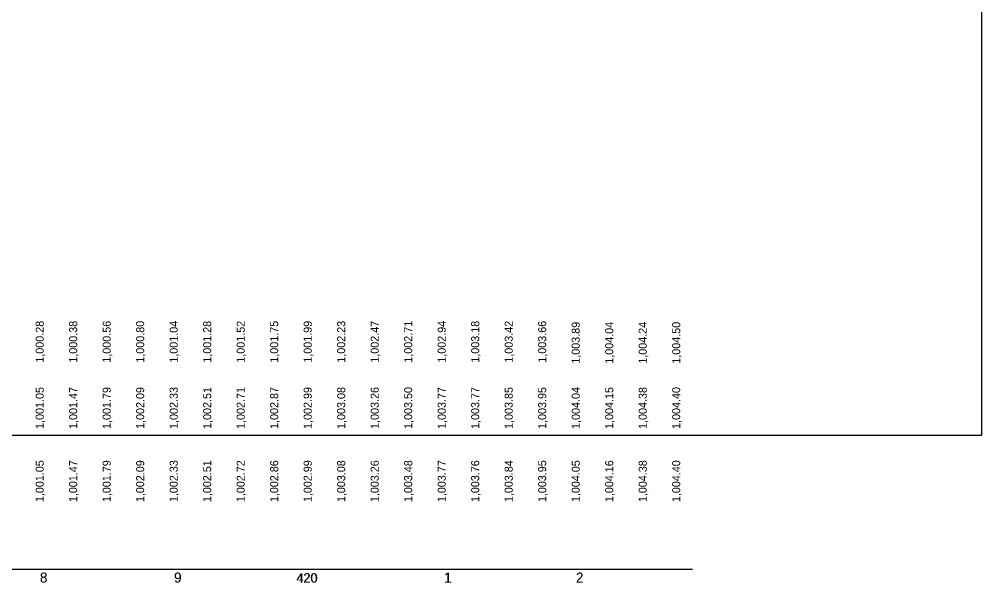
# Model space of a CAD drawing. Extents: x 150 to 16976893, y 3102 to 12559827.
# Drawn here: x 16976175 to 16976893, y 12558429 to 12558849 of the extents above; entities that cross this region are included whole.
import ezdxf

# ---------------------------------------------------------------- set-up
doc = ezdxf.new("R2010")
doc.units = 0
for name, color, linetype in [('Default', 7, 'Continuous'), ('Level 56', 7, 'Continuous'), ('RD_DDB_StaTX', 7, 'Continuous'), ('RD_DDB_StripGrade_EX', 7, 'Continuous'), ('RD_GPK_Profile_Cell', 7, 'Continuous')]:
    doc.layers.add(name, color=color, linetype=linetype)

msp = doc.modelspace()

# ---------------------------------------------------------------- linework, layer by layer
at = {"layer": 'Default'}
msp.add_lwpolyline([(16975392.9, 12558539.31), (16976892.9, 12558539.31), (16976892.9, 12559537.53), (16975392.9, 12559537.53)], close=True, dxfattribs=at)
at = {"layer": 'RD_GPK_Profile_Cell'}
msp.add_line((16972208.1, 12558439.31), (16976677.07, 12558439.31), dxfattribs=at)

# ---------------------------------------------------------------- texts
at = {"layer": 'Level 56'}
for s, p in [('1,000.28', (16976192.9, 12558593.29)), ('1,000.38', (16976217.9, 12558593.29)), ('1,000.56', (16976242.9, 12558593.29)), ('1,000.80', (16976267.9, 12558593.29)), ('1,001.04', (16976292.9, 12558593.29)), ('1,001.28', (16976317.9, 12558593.29)), ('1,001.52', (16976342.9, 12558593.29)), ('1,001.75', (16976367.9, 12558593.29)), ('1,001.99', (16976392.9, 12558593.29)), ('1,002.23', (16976417.9, 12558593.29)), ('1,002.47', (16976442.9, 12558593.29)), ('1,002.71', (16976467.9, 12558593.29)), ('1,002.94', (16976492.9, 12558593.29)), ('1,003.18', (16976517.9, 12558593.29)), ('1,003.42', (16976542.9, 12558593.29)), ('1,003.66', (16976567.9, 12558593.29)), ('1,003.89', (16976592.9, 12558592.52)), ('1,004.04', (16976617.9, 12558592.52)), ('1,004.24', (16976642.9, 12558592.52)), ('1,004.50', (16976667.9, 12558592.52)), ('1,001.05', (16976192.9, 12558489.31)), ('1,001.47', (16976217.9, 12558489.31)), ('1,001.79', (16976242.9, 12558489.31)), ('1,002.09', (16976267.9, 12558489.31)), ('1,002.33', (16976292.9, 12558489.31)), ('1,002.51', (16976317.9, 12558489.31)), ('1,002.72', (16976342.9, 12558489.31)), ('1,002.86', (16976367.9, 12558489.31)), ('1,002.99', (16976392.9, 12558489.31)), ('1,003.08', (16976417.9, 12558489.31)), ('1,003.26', (16976442.9, 12558489.31)), ('1,003.48', (16976467.9, 12558489.31)), ('1,003.77', (16976492.9, 12558489.31)), ('1,003.76', (16976517.9, 12558489.31)), ('1,003.84', (16976542.9, 12558489.31)), ('1,003.95', (16976567.9, 12558489.31)), ('1,004.05', (16976592.9, 12558489.31)), ('1,004.16', (16976617.9, 12558489.31)), ('1,004.38', (16976642.9, 12558489.31)), ('1,004.40', (16976667.9, 12558489.31))]:
    msp.add_text(s, height=6, rotation=90, dxfattribs=at).set_placement(p)
at = {"layer": 'RD_DDB_StaTX'}
for s, height, p in [('8', 7.5, (16976190.05, 12558429.31)), ('8', 7.5, (16976190.12, 12558429.31)), ('9', 7.5, (16976290.12, 12558429.31)), ('9', 7.5, (16976290.25, 12558429.31)), ('420', 7, (16976381.45, 12558429.31)), ('420', 7, (16976381.75, 12558429.31)), ('1', 7.5, (16976491.56, 12558429.31)), ('1', 7.5, (16976491.89, 12558429.31)), ('2', 7.5, (16976590.05, 12558429.31)), ('2', 7.5, (16976590.12, 12558429.31))]:
    msp.add_text(s, height=height, dxfattribs=at).set_placement(p)
at = {"layer": 'RD_DDB_StripGrade_EX'}
for s, p in [('1,001.05', (16976192.9, 12558543.9)), ('1,001.47', (16976217.9, 12558543.9)), ('1,001.79', (16976242.9, 12558543.9)), ('1,002.09', (16976267.9, 12558543.9)), ('1,002.33', (16976292.9, 12558543.9)), ('1,002.51', (16976317.9, 12558543.9)), ('1,002.71', (16976342.9, 12558543.9)), ('1,002.87', (16976367.9, 12558543.9)), ('1,002.99', (16976392.9, 12558543.9)), ('1,003.08', (16976417.9, 12558543.9)), ('1,003.26', (16976442.9, 12558543.9)), ('1,003.50', (16976467.9, 12558543.9)), ('1,003.77', (16976492.9, 12558543.9)), ('1,003.77', (16976517.9, 12558543.9)), ('1,003.85', (16976542.9, 12558543.9)), ('1,003.95', (16976567.9, 12558543.9)), ('1,004.04', (16976592.9, 12558543.9)), ('1,004.15', (16976617.9, 12558543.9)), ('1,004.38', (16976642.9, 12558543.9)), ('1,004.40', (16976667.9, 12558543.9))]:
    msp.add_text(s, height=6, rotation=90, dxfattribs=at).set_placement(p)

doc.saveas('drawing.dxf')
